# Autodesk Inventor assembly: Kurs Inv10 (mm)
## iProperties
Shininess: 64.0
Length Units: 11269
Angle Units: 11279
Time Units: 11290
Mass Units: 11283
Length Display Precision: 3
Angle Display Precision: 2
Compacted: True
Part Number: Kurs Inv10 (mm)
Document SubType Name: Assembly
Created: 2003-08
Designer: JWe
Manufacturer: Standard
Standards Organization: Custom
Density: 0.0
Volumn: 0.0
Area: 0.0
PropertySet Name: Model Information
Control State: 0
Master: False
Checked Out: False
Author: Administratör
